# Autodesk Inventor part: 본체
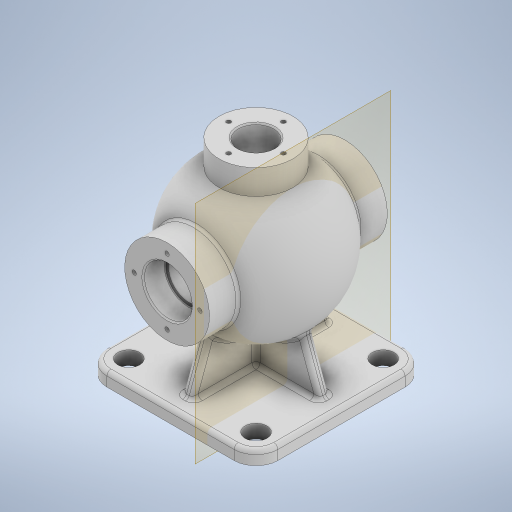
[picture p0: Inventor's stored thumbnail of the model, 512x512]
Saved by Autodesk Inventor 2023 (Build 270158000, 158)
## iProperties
Created: 2023-07
Part Number: 본체
Material: 일반
Document SubType Name: Modeling
Designer: Owner
Density: 1 g/cm^3
Appearance: 기본값
Author: Owner
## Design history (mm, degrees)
sketch "스케치1"
  geometry: L1 (62.5, 62.5)-(-62.5, 62.5); L2 (-62.5, 62.5)-(-62.5, -62.5); L3 (-62.5, -62.5)-(62.5, -62.5); L4 (62.5, -62.5)-(62.5, 62.5); L5 (62.5, 62.5)-(-62.5, -62.5); L6 (-62.5, 62.5)-(62.5, -62.5); 1 further point
  constraints: 12 end point, 2 midpoint, 2 parallel, 1 horizontal, 1 perpendicular
  dimensions: "d0" = 125 distance of L2.end L3.end; "d1" = 125 distance of L1.end L2.end
extrude "돌출1" new body sketch "스케치1" distance "d2" = 10; taper "d3" = 0 deg
sketch "스케치2"
  geometry: L1 (85, 65)-(85, -65); L2 (85, 65)-(116, 65); L3 (116, 65)-(116, 44.215); L4 (85, -65)-(116, -65); L5 (116, -65)-(116, -44.215); A1 r 54 centre (85, 0) between (116, -44.215) and (116, 44.215); 2 further points
  constraints: 10 end point, 2 horizontal, 2 perpendicular, 2 point on circle, 1 centre point, 1 coincident, 1 horizontal alignment, 1 midpoint, 1 parallel, 1 vertical
  dimensions: "d12" = 130 distance of L1.start L1.end; "d13" = 85 distance of point (0, 0) point (85, 0); "d14" = 108 diameter of A1; "d16" = 62 diameter of L5 L1
revolve "회전1" sketch "스케치2" stored, may be unused: angle "d17" = 90 deg
sketch "스케치3"
  geometry: C1 r 31 at (0, 0) reference; 2 further points
  constraints: 1 coincident
hole "구멍1" sketch "스케치3" at (0, 0) diameter "d18" = 35; stored, may be unused: countersink angle "d22" = 90 deg, drill point angle "d24" = 0 deg; dims "d19" = 6, "d20" = 4, "d21" = 2, "d23" = 16
sketch "스케치4"
  geometry: L1 (58.87, 32.713)-(10, 50.5); L2 (58.87, -32.713)-(10, -50.5); L3 (0, -62.5)-(10, -62.5) reference; L4 (67.5, 65)-(67.5, 49) reference; L5 (67.5, 49)-(102.5, 49) reference; L6 (102.5, 49)-(102.5, 65) reference; L7 (102.5, 65)-(116, 65) reference; L8 (116, 65)-(116, 44.215) reference; L9 (116, -44.215)-(116, -65) reference; L10 (116, -65)-(54, -65) reference; L11 (54, -65)-(54, -44.215) reference; L12 (54, 44.215)-(54, 65) reference; L13 (54, 65)-(67.5, 65) reference; L14 (10, -62.5)-(0, -62.5) reference; L15 (0, -62.5)-(0, 62.5) reference; L16 (0, 62.5)-(10, 62.5) reference; L17 (10, 62.5)-(10, -62.5) reference; L18 (58.87, 32.713)-(58.87, -32.713); A1 r 54 centre (85, 0) between (116, -44.215) and (116, 44.215) reference; A2 r 54 centre (85, 0) between (54, 44.215) and (54, -44.215) reference; 1 further point
  constraints: 6 end point, 2 point on line, 1 equal length
  dimensions: "d25" = 20 deg angle of L3 L2; "d26" = 20 deg angle of L1 L16; "d27" = 12 vertical distance of L15.end L1.end; "d29" = 12 distance from line of L14 L2.end; "d30" = 48.87013 horizontal distance of L1.start L1.end
  node "절단 모서리 투영1"
fillet "모깎기1" dims "d28" = 16
feature "리브1" dims "d31" = 1, "d32" = 8, "d33" = 0, "d34" = 0, "d35" = 1, "d36" = 1
sketch "스케치5"
  geometry: L1 (32.433, 59.64)-(50.5, 10); L2 (-32.433, 59.64)-(-50.5, 10); L3 (62.5, 0)-(-62.5, 0) reference; L4 (-62.5, 0)-(-62.5, 10) reference; L5 (-62.5, 10)-(-4, 10) reference; L6 (-4, 10)-(-4, 31.148) reference; L7 (4, 31.148)-(4, 10) reference; L8 (4, 10)-(62.5, 10) reference; L9 (62.5, 10)-(62.5, 0) reference; L10 (-32.433, 59.64)-(32.433, 59.64); A1 r 54 centre (0, 85) between (4, 31.148) and (-4, 31.148) reference; 1 further point
  constraints: 6 end point, 2 point on line, 1 horizontal
  dimensions: "d37" = 20 deg angle of L1 L9; "d38" = 20 deg angle of L2 L4; "d39" = 12 horizontal distance of L2.end L3.end; "d40" = 12 horizontal distance of L3.start L1.end; "d41" = 59.63953 distance between parallel lines of L3 L10
feature "리브2" sketch "스케치5" dims "d42" = 1, "d43" = 8, "d44" = 0, "d45" = 0, "d46" = 1, "d47" = 1
fillet "모깎기2" dims "d48" = 3
fillet "모깎기3" dims "d49" = 3
fillet "모깎기4" dims "d50" = 3
sketch "스케치6"
  geometry: C1 r 8 at (46.5, -46.5); C2 r 8 at (46.5, 46.5); C3 r 8 at (-46.5, -46.5); C4 r 8 at (-46.5, 46.5); A1 r 13 centre (46.5, -46.5) between (46.5, -59.5) and (59.5, -46.5) reference; A2 r 13 centre (46.5, 46.5) between (59.5, 46.5) and (46.5, 59.5) reference; A3 r 13 centre (-46.5, 46.5) between (-46.5, 59.5) and (-59.5, 46.5) reference; A4 r 13 centre (-46.5, -46.5) between (-59.5, -46.5) and (-46.5, -59.5) reference; 1 further point
  constraints: 4 centre point, 4 coincident
  dimensions: "d51" = 16 diameter of C1; "d52" = 16 diameter of C4; "d53" = 16 diameter of C2; "d54" = 16 diameter of C3
extrude "돌출2" cut sketch "스케치6" stored distance "d55" = 10; taper "d56" = 0 deg
sketch "스케치7"
  geometry: L1 (67.5, 65)-(67.5, 49) reference; L2 (67.5, 49)-(102.5, 49) reference; L3 (102.5, 49)-(102.5, 65) reference; L4 (102.5, 65)-(116, 65) reference; L5 (116, 65)-(116, 44.215) reference; L6 (116, -44.215)-(116, -65) reference; L7 (116, -65)-(54, -65) reference; L8 (54, -65)-(54, -44.215) reference; L9 (44.231, -38.041)-(11.974, -49.782) reference; L10 (10, -52.601)-(10, -59.5) reference; L11 (7, -62.5)-(0, -62.5) reference; L12 (0, -62.5)-(0, 62.5) reference; L13 (0, 62.5)-(7, 62.5) reference; L14 (10, 59.5)-(10, 52.601) reference; L15 (11.974, 49.782)-(44.231, 38.041) reference; L16 (54, 44.215)-(54, 65) reference; L17 (54, 65)-(67.5, 65) reference; L18 (54, -65)-(116, -65) reference; L19 (85, -65)-(85, 65); L20 (100, 49)-(100, 41.364); L21 (102.5, -65)-(102.5, -49); L22 (102.5, -49)-(100, -49); L23 (100, -49)-(100, -41.364); A1 r 54 centre (85, 0) between (116, -44.215) and (116, 44.215) reference; A2 r 54 centre (85, 0) between (47.349, -38.709) and (54, -44.215) reference; A3 r 3 centre (45.257, -40.86) between (47.349, -38.709) and (44.231, -38.041) reference; A4 r 3 centre (13, -52.601) between (11.974, -49.782) and (10, -52.601) reference; A5 r 3 centre (7, -59.5) between (7, -62.5) and (10, -59.5) reference; A6 r 3 centre (7, 59.5) between (10, 59.5) and (7, 62.5) reference; A7 r 3 centre (13, 52.601) between (10, 52.601) and (11.974, 49.782) reference; A8 r 3 centre (45.257, 40.86) between (44.231, 38.041) and (47.349, 38.709) reference; A9 r 54 centre (85, 0) between (54, 44.215) and (47.349, 38.709) reference; A10 r 44 centre (85, 0) between (100, -41.364) and (100, 41.364); 4 further points
  constraints: 10 end point, 3 perpendicular, 2 point on circle, 2 point on line, 2 vertical, 1 centre point, 1 coincident, 1 midpoint
  dimensions: "d57" = 88 diameter of A10; "d59" = 15 distance between parallel lines of L19 L20; "d60" = 15 distance between parallel lines of L19 L23; "d61" = 17.5 distance between parallel lines of L19 L21; "d62" = 16 distance between parallel lines of L7 L22
revolve "회전2" sketch "스케치7" stored, may be unused: angle "d63" = 90 deg
node "작업 평면1"
sketch "스케치8"
  geometry: C1 r 27 at (0, 0); 1 further point
  constraints: 1 centre point, 1 coincident
  dimensions: "d65" = 54 diameter of C1
extrude "돌출3" join sketch "스케치8" stored distance "d66" = 10; taper "d67" = 0 deg
sketch "스케치9"
  geometry: C1 r 27 at (0, 0) reference; 2 further points
  constraints: 1 coincident
hole "구멍2" sketch "스케치9" at (0, 0) diameter "d68" = 26; stored, may be unused: countersink angle "d72" = 90 deg, drill point angle "d74" = 0 deg; dims "d69" = 6, "d70" = 4, "d71" = 2, "d73" = 40
sketch "스케치10"
  geometry: C1 r 17.5 at (0, 0) reference; 2 further points
  constraints: 1 vertical alignment
  dimensions: "d75" = 24 distance of C1.centre point (0, 24)
hole "구멍3" sketch "스케치10" at (0, 24) diameter "d76" = 3.242; stored, may be unused: countersink angle "d80" = 90 deg, drill point angle "d82" = 118 deg; dims "d77" = 12, "d78" = 4, "d79" = 2, "d81" = 15
sketch "스케치11"
  geometry: C1 r 13 at (0, 0) reference; 1 further point
  constraints: 1 horizontal alignment
  dimensions: "d86" = 20 distance of C1.centre point (-20, 0)
hole "구멍4" sketch "스케치11" at (-20, 0) diameter "d87" = 3.242; stored, may be unused: countersink angle "d91" = 90 deg, drill point angle "d93" = 118 deg; dims "d88" = 9, "d89" = 4, "d90" = 2, "d92" = 11
fillet "모깎기5" dims "d97" = 3
chamfer "모따기1" distance "d98" = 1; stored, may be unused: second distance "d99" = 2, angle "d100" = 45 deg
chamfer "모따기2" distance "d101" = 1; stored, may be unused: second distance "d102" = 2, angle "d103" = 45 deg
fillet "모깎기6" dims "d104" = 0.6
fillet "모깎기7" dims "d105" = 0.6
node "작업 평면2"
sketch "스케치12"
  geometry: 1 further point
feature "Ư耀Ʊ耀Ƴ耀Ƶ耀Ʒ耀ƹ耀ƻ耀ƽ耀" dims "d0" = 125, "d1" = 125, "d2" = 10, "d3" = 0, "d12" = 130, "d13" = 85, "d14" = 108, "d16" = 62, "d17" = 90 deg, "d18" = 35, "d19" = 6, "d20" = 4, "d21" = 2, "d22" = 90 deg, "d23" = 16, "d24" = 0, "d25" = 20 deg, "d26" = 20 deg, "d27" = 12, "d28" = 16, "d29" = 12, "d30" = 48.87013, "d31" = 1, "d32" = 8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
node "솔리드1"
pattern_circular "원형 패턴1" dims angle "d84" = 360 deg
mirror "미러1"
pattern_circular "원형 패턴2" dims angle "d95" = 360 deg
node "절단 모서리 투영2"
node "절단 모서리 투영3"
feature "A9D066F2-1C7D-4E18-AEED-F7BC21143FA4" dims "d18" = 35, "d19" = 6, "d20" = 4, "d21" = 2, "d22" = 90 deg, "d23" = 16, "d24" = 0
